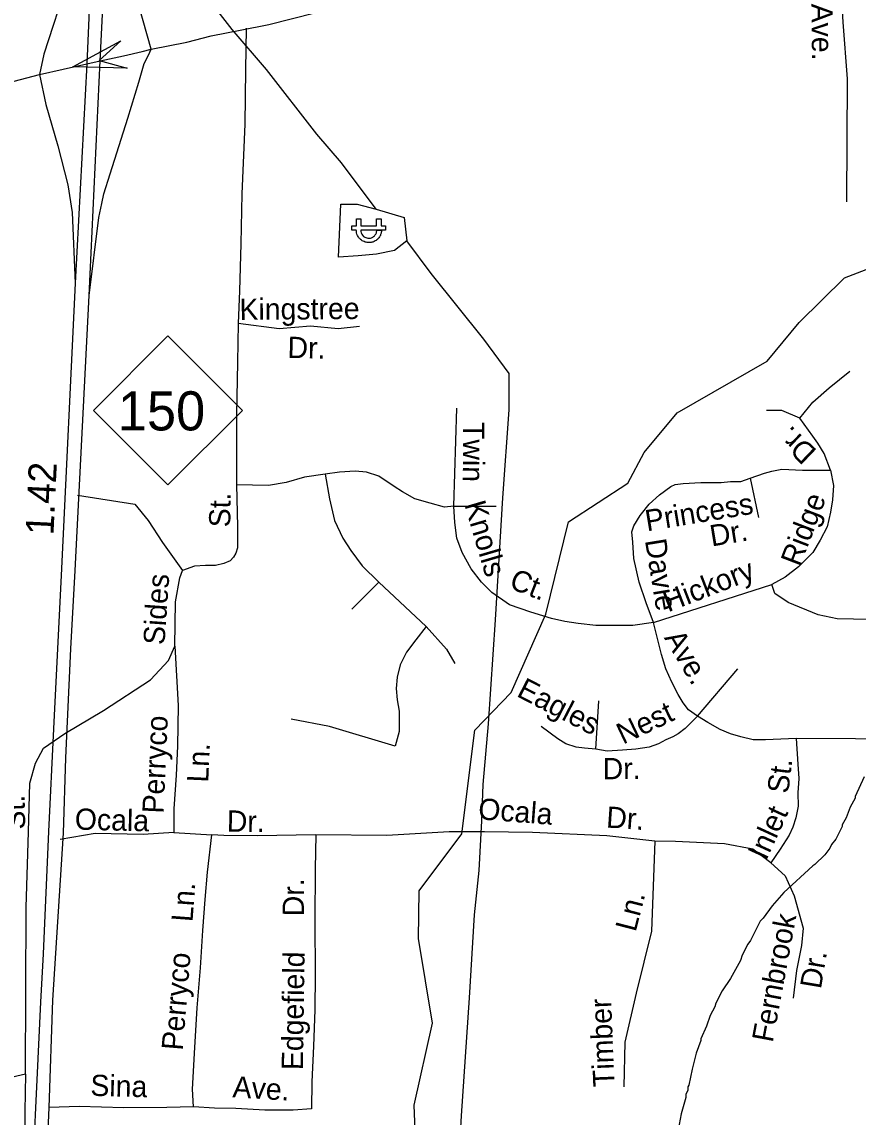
# Model space of a CAD drawing. Extents: x 1547597 to 1699558, y 810033 to 920809.
# Drawn here: x 1627167 to 1630904, y 831387 to 836281 of the extents above; entities that cross this region are included whole.
import ezdxf

# ---------------------------------------------------------------- set-up
doc = ezdxf.new("R2010")
doc.units = 0
for name, color, linetype in [('Exist Hydrographic Creek Single Shore', 7, 'Continuous'), ('Exist Hydrographic Misc Water Feature', 7, 'Continuous'), ('Exist Road Non-System Type 51', 7, 'Continuous'), ('Exist Road Non-System Type 51 Label', 7, 'Continuous'), ('Exist Road Primary Interstate Ramp 1 Lane Attributed', 7, 'Continuous'), ('Exist Road Primary NC Divided Attributed', 7, 'Continuous'), ('Exist Road Primary NC Service Mileage Hundredths English Label', 7, 'Continuous'), ('Exist Road Primary NC Shield CELL', 7, 'Continuous'), ('Exist Road Primary NC Shield Number Label', 7, 'Continuous'), ('Exist Road Secondary Structure Standard Bridge Attributed CELL', 7, 'Continuous'), ('Exist Road Secondary Type 51 Attributed', 7, 'Continuous'), ('Exist Utilities Electrical Power Substation CELL', 7, 'Continuous'), ('Exist Utilities Electrical Transmission Line', 7, 'Continuous')]:
    doc.layers.add(name, color=color, linetype=linetype)

msp = doc.modelspace()

# ---------------------------------------------------------------- linework, layer by layer
at = {"layer": 'Exist Hydrographic Creek Single Shore'}
for points in [[(1630497.7, 834764.4), (1630640.8, 834937.6), (1630842.8, 835137), (1631094.8, 835233.7), (1631386.8, 835296.7), (1631504.8, 835369.8), (1631783.9, 835751.5), (1631894.8, 835988.9), (1631913.9, 836165.7), (1631826.8, 836499.1), (1631801.8, 836525.8), (1631820.8, 836758.5), (1631907.8, 837058.7)], [(1628926.6, 831290.6), (1628919.6, 831439.9), (1629001.8, 831806.4), (1628939.8, 832185.2), (1628942.7, 832398.2), (1629132.3, 832653.6), (1629190.9, 833116), (1629353, 833285.1), (1629508.8, 833634.4), (1629609.5, 834047.6), (1629874.8, 834219.7), (1629948.5, 834357.4), (1630095.9, 834534.4), (1630497.7, 834764.4)]]:
    msp.add_lwpolyline(points, dxfattribs=at)
at = {"layer": 'Exist Hydrographic Misc Water Feature'}
for points in [[(1630932, 832908.1), (1630891.4, 832820.5), (1630891.3, 832812.5), (1630869, 832772.7), (1630850.8, 832724.9), (1630832.5, 832693.1), (1630832.4, 832685.1), (1630804.1, 832629.4), (1630786, 832605.5), (1630777.9, 832589.6), (1630755.6, 832559.8), (1630711.4, 832516.2), (1630701.4, 832510.3), (1630572.6, 832391.4), (1630520.3, 832331.8), (1630479.9, 832276.2), (1630466.6, 832263.4)], [(1630466.6, 832263.4), (1630423.6, 832175.7), (1630411.4, 832159.7), (1630386.7, 832111.2), (1630378.4, 832087.1), (1630333.3, 832007.2), (1630296.6, 831951.7), (1630267.9, 831896.1), (1630263.7, 831880.2), (1630243.1, 831840.5), (1630226.5, 831792.8), (1630201.8, 831737.1), (1630201.7, 831729.1), (1630180.9, 831673.4), (1630161.9, 831601.7), (1630146.9, 831529.9), (1630142.8, 831522), (1630142.6, 831506), (1630134.4, 831490.1), (1630134.2, 831474.1), (1630113.2, 831402.4), (1630096, 831306.7)]]:
    msp.add_lwpolyline(points, dxfattribs=at)
at = {"layer": 'Exist Road Non-System Type 51'}
for points in [[(1630819.3, 836550.8), (1630836.4, 836280.1), (1630854.7, 836026.2), (1630852.9, 835477.4)], [(1628169.5, 836253.3), (1628166.7, 836067), (1628162.8, 835824.2), (1628149.3, 835512.5), (1628145.5, 835288.9), (1628139.7, 835079.8), (1628133.9, 834933.4)], [(1628133.9, 834933.4), (1628130.1, 834760.3), (1628126.2, 834527.2), (1628126.2, 834213.1), (1628130.1, 834026.5), (1628130.1, 833930.2), (1628122.4, 833907.1), (1628113.1, 833888.5), (1628096.9, 833872.8), (1628068.7, 833861.1), (1628032.7, 833851.7), (1627986.7, 833852.4), (1627938.6, 833849), (1627884.9, 833829.5)], [(1628676.3, 834919.4), (1628580.2, 834908.8), (1628456.4, 834920.7), (1628316.5, 834908.7), (1628133.9, 834933.4)], [(1630643.7, 834510.2), (1630702, 834582), (1630775.5, 834646.4), (1630867.5, 834720)], [(1629097.2, 834117.3), (1629111, 834554.3)], [(1630643.7, 834510.2), (1630564, 834545.1), (1630495, 834545.1)], [(1630780.1, 834278.3), (1630752.5, 834351.9), (1630724.9, 834397.9), (1630702, 834430.1), (1630643.7, 834510.2)], [(1629097.2, 834117.3), (1629055.9, 834112.7), (1628991.5, 834131.1), (1628922.5, 834149.5), (1628867.3, 834181.7), (1628830.6, 834204.7), (1628761.6, 834250.7), (1628706.4, 834269.1), (1628655.8, 834273.7), (1628586.9, 834269.1), (1628522.5, 834259.9)], [(1630421.5, 834241.5), (1630485.8, 834264.5), (1630518, 834273.7), (1630564, 834282.9), (1630656, 834278.3), (1630780.1, 834278.3)], [(1630780.1, 834278.3), (1630793.9, 834209.3), (1630789.3, 834144.9), (1630780.1, 834089.7), (1630766.3, 834025.3), (1630734.1, 833965.4), (1630702, 833910.2), (1630637.6, 833845.8), (1630577.8, 833799.8), (1630518, 833767.6)], [(1628522.5, 834259.9), (1628430.5, 834246.1), (1628347.8, 834223.1), (1628269.6, 834209.3), (1628126.2, 834213.1)], [(1628522.5, 834259.9), (1628540.9, 834149.5), (1628563.9, 834052.9), (1628600.7, 833974.6), (1628637.4, 833919.4), (1628688, 833850.4), (1628761.6, 833776.8)], [(1629897.3, 833956.2), (1629892.7, 834002.3), (1629901.9, 834029.9), (1629929.5, 834075.9), (1629970.9, 834126.5), (1630016.8, 834167.9), (1630067.4, 834204.7), (1630085.8, 834213.9), (1630122.6, 834218.5), (1630200.8, 834223.1), (1630292.7, 834223.1), (1630334.1, 834227.7), (1630380.1, 834227.7), (1630421.5, 834241.5)], [(1630421.5, 834241.5), (1630458.3, 834066.7)], [(1627415.4, 834166.7), (1627671, 834126.6), (1627731.7, 834053.1), (1627795.5, 833954.1), (1627884.9, 833829.5)], [(1629989.3, 833597.4), (1629897.3, 833583.6), (1629809.9, 833583.6), (1629731.8, 833583.6), (1629653.6, 833592.8), (1629593.8, 833602), (1629534.1, 833615.8), (1629442.1, 833643.4), (1629345.5, 833675.6), (1629267.4, 833730.8), (1629221.4, 833776.8), (1629175.4, 833836.6), (1629134, 833910.2), (1629111, 833974.6), (1629101.8, 834043.7), (1629097.2, 834117.3)], [(1629097.2, 834117.3), (1629285.8, 834117.3)], [(1629989.3, 833597.4), (1629957.1, 833684.8), (1629924.9, 833776.8), (1629901.9, 833882.6), (1629897.3, 833956.2)], [(1627849.9, 833491.6), (1627853, 833688.9), (1627872.1, 833797.5), (1627884.9, 833829.5)], [(1628761.6, 833776.8), (1628642, 833657.2)], [(1628761.6, 833776.8), (1628973.1, 833579)], [(1629989.3, 833597.4), (1630518, 833767.6)], [(1632103.5, 833610.9), (1631459.8, 833627.1), (1631187.2, 833627.1), (1631064.8, 833622.5), (1630956.2, 833610.9), (1630810.7, 833613.2), (1630725.3, 833631.7), (1630591.3, 833687.2), (1630531.3, 833726.5), (1630518, 833767.6)], [(1630187, 833178.7), (1630145.6, 833206.3), (1630122.6, 833238.5), (1630099.6, 833275.3), (1630072, 833330.5), (1630044.4, 833390.3), (1630026, 833454.8), (1629989.3, 833597.4)], [(1628973.1, 833579), (1628927.1, 833519.2), (1628885.7, 833464), (1628858.1, 833408.7), (1628844.4, 833353.5), (1628839.8, 833302.9), (1628844.4, 833252.3), (1628853.6, 833201.7), (1628853.6, 833151.1), (1628853.6, 833109.7), (1628835.2, 833045.3), (1628540.9, 833132.7), (1628370.8, 833164.9)], [(1628973.1, 833579), (1629065.1, 833477.8), (1629101.8, 833413.4)], [(1627358.3, 833101.8), (1627530.7, 833204.1), (1627741.4, 833341.4), (1627821.2, 833427.7), (1627849.9, 833491.6)], [(1627849.9, 833491.6), (1627865.3, 833226.5), (1627862.4, 833044.7), (1627856.6, 832914.9), (1627846.1, 832765), (1627846.1, 832658.8)], [(1630187, 833178.7), (1630366.3, 833390.3)], [(1629731.8, 833031.5), (1629745.6, 833247.7)], [(1630187, 833178.7), (1630131.8, 833123.5), (1630099.6, 833100.5), (1630076.6, 833086.7), (1630044.4, 833072.9), (1630012.2, 833054.5), (1629970.9, 833040.7), (1629911.1, 833031.5), (1629851.3, 833026.9), (1629782.3, 833022.3), (1629731.8, 833031.5)], [(1630627.2, 833078.7), (1630490.4, 833072.9), (1630435.3, 833072.9), (1630380.1, 833086.7), (1630334.1, 833100.5), (1630288.1, 833118.9), (1630233, 833151.1), (1630187, 833178.7)], [(1627182.9, 831579.4), (1627186.1, 832323.8), (1627195.7, 832662.4), (1627202.1, 832879.7), (1627227.6, 832969.1), (1627262.7, 833036.2), (1627358.3, 833101.8)], [(1629731.8, 833031.5), (1629681.2, 833036.1), (1629644.4, 833040.7), (1629598.4, 833054.5), (1629561.6, 833077.5), (1629488.1, 833132.7)], [(1630627.2, 833078.7), (1630634.2, 832963.5), (1630638.9, 832900.1), (1630634.2, 832836.6), (1630635.7, 832776.1), (1630625.2, 832724.3), (1630612.4, 832682.2), (1630596.5, 832647.5), (1630556, 832584.9), (1630513.6, 832523.9)], [(1631157.9, 833076.4), (1630627.2, 833078.7)], [(1627846.1, 832658.8), (1627709.3, 832649.8), (1627493.7, 832654.9), (1627337.7, 832627.1)], [(1627846.1, 832658.8), (1628016.3, 832648.5)], [(1629995.4, 832620.5), (1629781, 832643.5), (1629449.2, 832658.8), (1629234.8, 832661.4), (1629076.6, 832661.4), (1628797.3, 832645.9), (1628480.8, 832648.5)], [(1627933.8, 831432.7), (1627929, 831512.7), (1627940, 831698.3), (1627950.6, 831876.2), (1627965.2, 832053.8), (1627975.8, 832221.5), (1627986, 832359.4), (1627995.7, 832481.1), (1628016.3, 832648.5)], [(1628480.8, 832648.5), (1628217.9, 832643.4), (1628069.9, 832645.9), (1628016.3, 832648.5)], [(1628480.8, 832648.5), (1628477.4, 832495.9), (1628475.9, 832264), (1628478.2, 832022.2), (1628475.9, 831866.4), (1628469.4, 831704.4), (1628462.9, 831544.7), (1628461.1, 831424.8)], [(1629995.4, 832620.5), (1629980.2, 832218.4), (1629912.6, 831940.7), (1629861.3, 831721.4), (1629856.6, 831523.1)], [(1630513.6, 832523.9), (1630434.4, 832584.7), (1630306.8, 832607.7), (1630087.3, 832618), (1629995.4, 832620.5)], [(1630513.6, 832523.9), (1630577.8, 832464.8), (1630618, 832375.3), (1630658.1, 832231), (1630650.8, 832154.3), (1630628.9, 832042.8), (1630614.3, 831918.6)], [(1627182.9, 831579.4), (1627098.7, 831559.1), (1626984.7, 831554.8), (1626852.6, 831538.7), (1626686.3, 831513.3)], [(1627182.9, 831579.4), (1627180.3, 831411.8), (1627180.3, 831300), (1627189.7, 831239.9), (1627255.5, 831229)], [(1627933.8, 831432.7), (1627813.9, 831430.6), (1627622.1, 831429.2), (1627422.3, 831434.3), (1627289, 831430.3)], [(1628461.1, 831424.8), (1628379.1, 831418.1), (1628253.2, 831417.8), (1628123.5, 831425.9), (1628027.7, 831427.2), (1627933.8, 831432.7)]]:
    msp.add_lwpolyline(points, dxfattribs=at)
at = {"layer": 'Exist Road Primary Interstate Ramp 1 Lane Attributed'}
for points in [[(1627503.3, 837132.5), (1627478, 836913.5), (1627469.3, 836850.9), (1627449.1, 836746), (1627417.2, 836622.1), (1627370.1, 836462.2), (1627265.3, 836136.5), (1627244.9, 836045.8)], [(1627743.9, 836159), (1627670.1, 836423.9), (1627630.6, 836569.7), (1627589.5, 836712.2), (1627583.8, 836809.5), (1627578.1, 836888.5), (1627577.1, 836961.7), (1627570.6, 837131)], [(1627466.7, 835058.6), (1627510.2, 835406.6), (1627523.3, 835469.6), (1627532.4, 835512.4), (1627561.2, 835601.5), (1627639.8, 835850.5), (1627689.5, 836011), (1627713, 836094.7), (1627732.9, 836132.2), (1627743.9, 836159)], [(1627244.9, 836045.8), (1627274.4, 835912.1), (1627326.8, 835727.3), (1627372.7, 835553), (1627391, 835428.9), (1627405.2, 835113.5)]]:
    msp.add_lwpolyline(points, dxfattribs=at)
at = {"layer": 'Exist Road Primary NC Divided Attributed'}
for points in [[(1627503.3, 837132.5), (1627500.4, 836925.2), (1627491.4, 836753.1), (1627472.3, 836437), (1627457.3, 836093.1)], [(1627517.1, 836107.5), (1627537.6, 836524), (1627554.9, 836945.3), (1627570.6, 837131)], [(1627457.3, 836093.1), (1627405.2, 835113.5)], [(1627466.7, 835058.6), (1627517.1, 836107.5)], [(1627405.2, 835113.5), (1627343.2, 833839.2), (1627307.8, 833121.5), (1627285.6, 832663), (1627261.3, 832116.9), (1627250.2, 831901), (1627233.6, 831553.2), (1627217, 831208.7), (1627184.8, 830524.3), (1627170.4, 830211.9), (1627147.2, 829708), (1627121.7, 829152), (1627102.3, 828828), (1627099, 828666.9), (1627086.8, 828465.9), (1627078, 828272), (1627056.4, 827891), (1627047.5, 827666.7), (1627039.2, 827471.3), (1627021.5, 827250.3)], [(1627088.5, 827252), (1627105.7, 827635.2), (1627143.3, 828251), (1627208.1, 829719.1), (1627245.8, 830508.8), (1627279, 831223.1), (1627289, 831430.3), (1627305.6, 831909.8), (1627353.2, 832656.3), (1627363.2, 832993), (1627385.3, 833479.3), (1627404.2, 833829.5), (1627466.7, 835058.6)]]:
    msp.add_lwpolyline(points, dxfattribs=at)
at = {"layer": 'Exist Road Primary NC Shield CELL'}
msp.add_lwpolyline([(1627486.4, 834545.1), (1627819.4, 834878.1), (1628152.4, 834545.1), (1627819.4, 834212.1)], close=True, dxfattribs=at)
at = {"layer": 'Exist Road Secondary Structure Standard Bridge Attributed CELL'}
msp.add_lwpolyline([(1627637.8, 836073.8), (1627394.1, 836080.3), (1627608.4, 836196.5), (1627512.6, 836108.7)], close=True, dxfattribs=at)
at = {"layer": 'Exist Road Secondary Type 51 Attributed'}
for points in [[(1627743.9, 836159), (1627903.9, 836190.8), (1628013.1, 836218.1), (1628142, 836244.5), (1628270.2, 836269.5), (1628475.7, 836322)], [(1627517.1, 836107.5), (1627620.7, 836129.7), (1627703.7, 836148.9), (1627743.9, 836159)], [(1627244.9, 836045.8), (1627457.3, 836093.1)], [(1627457.3, 836093.1), (1627517.1, 836107.5)], [(1626193.5, 835706.8), (1626336.2, 835749.2), (1626549.4, 835828.1), (1626775.1, 835898.9), (1626879.1, 835939.3), (1627076.1, 836000.8), (1627244.9, 836045.8)]]:
    msp.add_lwpolyline(points, dxfattribs=at)
at = {"layer": 'Exist Utilities Electrical Power Substation CELL'}
msp.add_lwpolyline([(1628642, 835369.3), (1628661.6, 835369.3), (1628661.6, 835401.5), (1628681.4, 835401.5), (1628681.4, 835369.3), (1628752.2, 835369.3), (1628752.2, 835401.5), (1628772, 835401.5), (1628772, 835369.3), (1628791.6, 835369.3), (1628791.6, 835349.8), (1628772, 835349.8), (1628752.2, 835349.8), (1628681.4, 835349.8), (1628682, 835343.7), (1628683.2, 835338.3), (1628685.7, 835332.7), (1628689.4, 835327.3), (1628694, 835322.5), (1628696.6, 835320.5), (1628699.7, 835318.8), (1628703.5, 835316.8), (1628707.7, 835315.4), (1628712.4, 835314.5), (1628716.1, 835314.2), (1628720.3, 835314.4), (1628725, 835315.1), (1628729.3, 835316.3), (1628732.2, 835317.5), (1628735.6, 835319.3), (1628738.9, 835321.7), (1628742.1, 835324.5), (1628744.8, 835327.5), (1628746.9, 835330.4), (1628748.2, 835332.7), (1628749.7, 835335.5), (1628751, 835339), (1628751.5, 835341.3), (1628752.3, 835345), (1628752.5, 835347.8), (1628752.7, 835349.8), (1628774.3, 835349.9), (1628774, 835346.4), (1628773.6, 835343.7), (1628773.1, 835340.4), (1628772.3, 835337.1), (1628771.3, 835333.3), (1628770.2, 835330.2), (1628768.9, 835327), (1628767.1, 835323.5), (1628764.8, 835319.9), (1628762.3, 835316.3), (1628759.7, 835313.3), (1628757, 835310.5), (1628753.4, 835307.3), (1628749.6, 835304.4), (1628745.4, 835301.9), (1628741, 835299.6), (1628737.7, 835298.2), (1628734.5, 835297.2), (1628731.4, 835296.4), (1628727.6, 835295.5), (1628723.8, 835295.1), (1628720.4, 835294.7), (1628716, 835294.7), (1628713, 835294.9), (1628709.6, 835295.3), (1628706, 835296), (1628701.2, 835297.1), (1628696.1, 835299), (1628691.7, 835301), (1628688.1, 835303.1), (1628683.9, 835305.8), (1628680.8, 835308.5), (1628678.9, 835310.1), (1628676.5, 835312.6), (1628674.5, 835314.8), (1628671.8, 835318.1), (1628669.1, 835322.3), (1628667.1, 835326.1), (1628665.6, 835329.4), (1628664.4, 835332.6), (1628662.8, 835337.8), (1628662, 835342.1), (1628661.6, 835345.9), (1628661.3, 835349.8), (1628642, 835349.8)], close=True, dxfattribs=at)
at = {"layer": 'Exist Utilities Electrical Transmission Line'}
for points in [[(1628749.4, 835444.8), (1628594.9, 835651.1), (1628484.8, 835778.8), (1628259.7, 836068.1), (1628106.7, 836246.3), (1627955.8, 836442.5)], [(1628887, 835302.8), (1628832.5, 835259.6), (1628752.3, 835242.9), (1628670.1, 835236.1), (1628582.1, 835229.5), (1628591.9, 835467.2), (1628665.8, 835466.1), (1628749.4, 835444.8)], [(1628749.4, 835444.8), (1628874.7, 835406.9), (1628887, 835302.8)], [(1629103.4, 830901.7), (1629131.2, 831393), (1629167.5, 831920.2), (1629189.3, 832291.6), (1629210.3, 832489.2), (1629221.8, 832710.9), (1629228.5, 832872.7), (1629252.6, 833144.1), (1629284, 833609.6), (1629316.5, 834154.8), (1629344.7, 834548.1), (1629345.2, 834709.9), (1629231.8, 834863.7), (1628996.7, 835157), (1628887, 835302.8)]]:
    msp.add_lwpolyline(points, dxfattribs=at)

# ---------------------------------------------------------------- texts
at = {"layer": 'Exist Road Non-System Type 51 Label'}
for s, rotation, p in [('Ave.', 270.4569, (1630695.8, 836362.1)), ('Kingstree', 0.4633, (1628139.6, 834949.1)), ('Dr.', 358.5104, (1628353, 834779.7)), ('Twin', 269.6209, (1629138.9, 834493.4)), ('Dr.', 136.2922, (1630724.2, 834364.8)), ('Ridge', 69.0221, (1630644, 833843)), ('St.', 89.0978, (1628097.8, 834022.1)), ('Knolls', 286.3616, (1629143.7, 834126)), ('Princess', 9.4371, (1629960.6, 834004.2)), ('Dr.', 9.4371, (1630249.8, 833936.6)), ('Davie', 279.3003, (1629951, 833964.2)), ('Ct.', 338.7031, (1629340.1, 833752.3)), ('Hickory', 21.2058, (1630054.6, 833642.3)), ('Sides', 86.0208, (1627803.8, 833494.8)), ('Ave.', 300.7053, (1630035.5, 833528.9)), ('Eagles', 332.6075, (1629373.5, 833269.8)), ('Nest', 25.5099, (1629853.5, 833050.8)), ('Perryco', 87.4244, (1627799.6, 832742.2)), ('Ln.', 87.4244, (1627999.4, 832880.9)), ('Dr.', 0.4655, (1629763, 832896.6)), ('St.', 83.1241, (1630592, 832830.2)), ('St.', 91.2788, (1627181.9, 832672.7)), ('Ocala', 355.6616, (1629203.9, 832718.3)), ('Ocala', 358.6254, (1627402.4, 832671.9)), ('Dr.', 359.1674, (1628082.2, 832662.8)), ('Dr.', 356.094, (1629776.3, 832681.3)), ('Inlet', 65.3624, (1630493.4, 832530.7)), ('Ln.', 85.7688, (1627929.1, 832257.2)), ('Dr.', 89.6287, (1628426.8, 832284.5)), ('Ln.', 75.5384, (1629909.7, 832211.5)), ('Fernbrook', 79.4081, (1630522.3, 831717.4)), ('Perryco', 85.2974, (1627885.3, 831682.8)), ('Edgefield', 89.1316, (1628422.6, 831596.7)), ('Dr.', 80.4747, (1630737.8, 831956.7)), ('Timber', 92.2756, (1629815.7, 831523.6)), ('Sina', 358.5515, (1627472, 831482.3)), ('Ave.', 356.4553, (1628106.6, 831476.2))]:
    msp.add_text(s, height=95, rotation=rotation, dxfattribs=at).set_placement(p)
at = {"layer": 'Exist Road Primary NC Service Mileage Hundredths English Label'}
msp.add_text('1.42', height=125, rotation=87.2688, dxfattribs=at).set_placement((1627307.6, 833985.9))
at = {"layer": 'Exist Road Primary NC Shield Number Label'}
msp.add_text('150', height=175, dxfattribs=at).set_placement((1627595.5, 834455.4))

doc.saveas('drawing.dxf')
